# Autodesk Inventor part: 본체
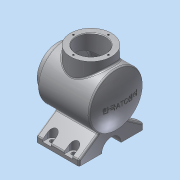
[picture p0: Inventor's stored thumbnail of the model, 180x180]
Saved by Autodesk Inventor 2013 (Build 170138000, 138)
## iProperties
Created: 2017-04
Part Number: 본체
Material: 알루미늄 6061
Document SubType Name: Modeling
Designer: dgall
Density: 2.71 g/cm^3
Mass: 1670.99 g
Surface Area: 1067.83 cm^2
Volume: 616.603 cm^3
Author: dgall
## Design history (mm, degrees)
sketch "스케치1"
  geometry: L1 (-60, 0)-(-60, 38); L2 (-60, 38)-(-48, 38); L3 (-48, 38)-(-48, 50); L4 (-48, 50)-(48.336, 50); L5 (-60, 0)-(60, 0); A1 r 113 centre (-53, 0) between (60, 0) and (48.336, 50); 2 further points
  constraints: 10 end point, 3 parallel, 2 point on circle, 1 centre point, 1 coincident, 1 horizontal alignment, 1 midpoint, 1 perpendicular, 1 vertical
  dimensions: "d0" = 76 diameter of L2 L5; "d2" = 100 diameter of L4 L5; "d3" = 113 radius of A1; "d4" = 12 distance of L1.end L2.end; "d5" = 108 horizontal distance of L5.end L3.end
revolve "회전1" sketch "스케치1" stored, may be unused: angle "d6" = 90 deg
sketch "스케치2"
  geometry: L1 (-48, -38)-(-60, -38) reference; L2 (-60, -38)-(-60, 38) reference; L3 (-60, 38)-(-48, 38) reference; L4 (-48, 38)-(-48, 50) reference; L5 (-48, 50)-(48.336, 50) reference; L6 (48.336, -50)-(-48, -50) reference; L7 (-48, -50)-(-48, -38) reference; L8 (-60, 27)-(-38, 27); L9 (-38, 27)-(-38, 40); L10 (-38, 40)-(41.916, 40); L11 (50, 0)-(-60, 0); A1 r 113 centre (-53, 0) between (48.336, -50) and (48.336, 50) reference; A2 r 103 centre (-53, 0) between (50, 0) and (41.916, 40); 1 further point
  constraints: 8 end point, 2 horizontal alignment, 2 perpendicular, 2 point on circle, 1 centre point, 1 concentric, 1 midpoint, 1 parallel, 1 point on line
  dimensions: "d7" = 10 radial gap between concentric circles of A1 A2; "d8" = 54 diameter of L8 L11; "d9" = 80 diameter of L10 L11; "d10" = 22 distance of L8.start L8.end
revolve "회전2" sketch "스케치2" stored, may be unused: angle "d11" = 90 deg
fillet "모깎기1" dims "d12" = 3
chamfer "모따기1" distance "d13" = 1; stored, may be unused: second distance "d14" = 2, angle "d15" = 45 deg
node "작업 평면1"
sketch "스케치3"
  geometry: L1 (60, 38)-(60, -38) reference; C1 r 38 at (-2, 0); 1 further point
  constraints: 1 centre point, 1 horizontal alignment
  dimensions: "d17" = 38 radius of C1; "d18" = 62 distance from line of L1 C1.centre
extrude "돌출1" join sketch "스케치3" stored distance "d19" = 10; taper "d20" = 0 deg
hole "구멍1" diameter "d23" = 54; stored, may be unused: countersink angle "d27" = 90 deg, drill point angle "d29" = 0 deg; dims "d21" = 10, "d22" = 10, "d24" = 6, "d25" = 4, "d26" = 2, "d28" = 8
sketch "스케치4"
  geometry: C1 r 27 at (0, 0) reference; C2 r 27 at (0, 0) reference; C3 r 38 at (0, 0) reference; 2 further points
  constraints: 1 vertical alignment
  dimensions: "d30" = 32.5 distance of C1.centre point (0, 32.5)
hole "구멍2" sketch "스케치4" at (0, 32.5) diameter "d31" = 3.242; stored, may be unused: countersink angle "d35" = 90 deg, drill point angle "d37" = 120 deg; dims "d32" = 8, "d33" = 4, "d34" = 2, "d36" = 10
sketch "스케치5"
  geometry: C1 r 38 at (0, 0) reference; C2 r 28 at (0, 0) reference; C3 r 38 at (0, 0) reference; 1 further point
  constraints: 1 vertical alignment
  dimensions: "d41" = 32.5 distance of C1.centre point (0, 32.5)
hole "구멍3" sketch "스케치5" at (0, 32.5) diameter "d42" = 3.242; stored, may be unused: countersink angle "d46" = 90 deg, drill point angle "d48" = 120 deg; dims "d43" = 8, "d44" = 4, "d45" = 2, "d47" = 10
sketch "스케치6"
  geometry: L1 (32.558, 37.947)-(65, 37.947) reference; L2 (65, 37.947)-(65, 26.926) reference; L3 (65, 26.926)-(29.58, 26.926) reference; L4 (29.58, -26.926)-(65, -26.926) reference; L5 (65, -26.926)-(65, -37.947) reference; L6 (65, -37.947)-(32.558, -37.947) reference; L7 (-45.101, 21.584)-(-72, 60); L8 (-72, 60)-(-82, 60); L9 (-82, 60)-(-82, -60); L10 (-82, -60)-(-72, -60); L11 (-72, -60)-(-45.101, -21.584); A1 r 50 centre (0, 0) between (32.558, 37.947) and (32.558, -37.947) reference; A2 r 40 centre (0, 0) between (29.58, 26.926) and (29.58, -26.926) reference; A3 r 50 centre (0, 0) between (-45.101, 21.584) and (-45.101, -21.584); 2 further points
  constraints: 10 end point, 4 point on circle, 2 parallel, 2 perpendicular, 1 centre point, 1 concentric, 1 horizontal alignment, 1 midpoint
  dimensions: "d52" = 120 distance of L8.end L9.end; "d54" = 10 distance of L9.end L10.end; "d55" = 55 deg angle of L8 L7; "d56" = 55 deg angle of L10 L11; "d57" = 82 distance from line of A1.centre L9
extrude "돌출2" join sketch "스케치6" stored distance "d58" = 80; taper "d59" = 0 deg
sketch "스케치7"
  geometry: L1 (21.584, -45.101)-(60, -72) reference; L2 (60, -72)-(60, -82) reference; L3 (60, -82)-(-60, -82) reference; L4 (-60, -82)-(-60, -72) reference; L5 (-60, -72)-(-21.584, -45.101) reference; L6 (0, 65)-(0, 50) reference; C1 r 39.998 at (0, 0) reference; C2 r 18 at (0, -82); A1 r 50 centre (0, 0) between (21.584, -45.101) and (0, 50) reference; A2 r 50 centre (0, 0) between (0, 50) and (-21.584, -45.101) reference; A3 r 50 centre (0, 0) between (-21.584, -45.101) and (21.584, -45.101) reference
  constraints: 1 centre point, 1 midpoint
  dimensions: "d60" = 18 radius of C2
extrude "돌출3" cut sketch "스케치7" stored distance "d61" = 80; taper "d62" = 0 deg
node "작업 평면2"
sketch "스케치8"
  geometry: L1 (0, -76.971)-(80, -76.971) reference; L2 (80, -76.971)-(80, -120) reference; L3 (80, -120)-(0, -120) reference; L4 (0, -120)-(0, -76.971) reference; L5 (80, -43.029)-(0, -43.029) reference; L6 (0, -43.029)-(0, 0) reference; L7 (0, 0)-(80, 0) reference; L8 (80, 0)-(80, -43.029) reference; L9 (12, 0)-(12, -10); L10 (28, -10)-(28, 0); A1 r 8 centre (20, -10) between (12, -10) and (28, -10); 1 further point
  constraints: 4 end point, 2 point on circle, 2 point on line, 2 tangent, 1 centre point, 1 parallel, 1 perpendicular
  dimensions: "d64" = 8 radius of A1; "d66" = 20 horizontal distance of A1.centre L6.end; "d67" = 10 distance of L9.start L9.end
extrude "돌출4" cut sketch "스케치8" distance "d68" = 20; taper "d69" = 0 deg
hole "구멍4" diameter "d72" = 8; stored, may be unused: countersink angle "d76" = 90 deg, drill point angle "d78" = 120 deg; dims "d70" = 10, "d71" = 10, "d73" = 8, "d74" = 4, "d75" = 2, "d77" = 10
fillet "모깎기2" dims "d82" = 3
fillet "모깎기3" dims "d83" = 3
node "작업 평면3"
sketch "스케치9"
  geometry: 2 further points
  constraints: 1 coincident, 1 other
feature "엠보싱1" sketch "스케치9" dims "d0" = 76, "d2" = 100, "d3" = 113, "d4" = 12, "d5" = 108, "d85" = 0.5, "d86" = 0
chamfer "모따기2" distance "d87" = 1; stored, may be unused: second distance "d88" = 2, angle "d89" = 45 deg
node "솔리드1"
pattern_circular "원형 패턴1" dims angle "d39" = 360 deg
pattern_circular "원형 패턴2" dims angle "d50" = 360 deg
pattern_linear "직사각형 패턴1"
mirror "대칭1"
node "절단 모서리 투영1"
node "절단 모서리 투영2"
node "절단 모서리 투영3"
node "절단 모서리 투영4"
node "절단 모서리 투영5"
node "절단 모서리 투영6"
other parameters: "d16" = 65, "d63" = -6, "d84" = -108
